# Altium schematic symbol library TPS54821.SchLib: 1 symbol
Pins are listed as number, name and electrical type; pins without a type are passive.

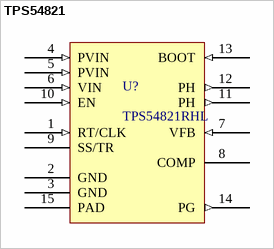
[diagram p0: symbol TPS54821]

## TPS54821
designator U?, comment TPS54821RHL
footprint RHL14
pins: 1 RT/CLK (in), 2 GND (power), 3 GND (power), 4 PVIN (in), 5 PVIN (in), 6 VIN (in), 7 VFB (in), 8 COMP, 9 SS/TR, 10 EN (in), 11 PH (out), 12 PH (out), 13 BOOT (in), 14 PG (out), 15 PAD (power)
